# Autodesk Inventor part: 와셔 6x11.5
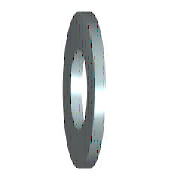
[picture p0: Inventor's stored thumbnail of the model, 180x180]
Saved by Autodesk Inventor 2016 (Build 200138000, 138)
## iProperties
IsCustomPart: 1
Created: 2012-02
Part Number: 와셔 6x11.5
Material: 강철, 연강
Description: 평면 와셔
Document SubType Name: Modeling
Standard: KS B 1326
Designer: mduedu
Standards Organization: KS
Language: ko-KR
Size Designation: 6x11.5
Categories: <MemberInstance><Categories><Category DisplayName="조임쇠" InternalName="e4da775c-781d-43d5-af7c-5136215cf5a6" Mnemonic="FSTN"><Category DisplayName="와셔" InternalN
Density: 1 g/cm^3
Appearance: 분홍색
Author: mduedu
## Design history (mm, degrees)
sketch "스케치"
  geometry: C1 r 5.75 at (0, 0); C2 r 3.2 at (0, 0); 1 further point
  constraints: 2 centre point, 2 coincident
  dimensions: "d0" = 6.4 diameter of C2 (= SD1); "d1" = 11.5 diameter of C1 (= SD2)
extrude "본체" new body sketch "스케치" distance "d2" = 1.6 (= SD); taper "d3" = 0 deg
workaxis "Work Axis1"
workplane "Work Plane1"
body "Solid1"
other parameters: "SD1" = 6.4 [user parameter; used in 1 equation term], "SD2" = 11.5 [user parameter; used in 1 equation term], "SD" = 1.6 [user parameter; used in 1 equation term], "d4" = 0, "d5" = 0, "d6" = 0, "d7" = 0, "NND" = 6 [user parameter]
